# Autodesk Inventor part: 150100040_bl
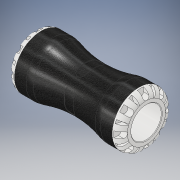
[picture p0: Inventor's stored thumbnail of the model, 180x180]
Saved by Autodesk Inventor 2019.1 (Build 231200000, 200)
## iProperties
Created: 2016-12
Part Number: 150100040_bl
Material: PVC-Piping
Description: PLASSON G-PLASS COUPLING 40X40
Document SubType Name: Modeling
Designer: KIM
Mass: 95.2094 g
Surface Area: 200.83 cm^2
Volume: 68.0067 cm^3
Density: 1.4 g/cm^3
Appearance: White
ILogicFactory: False
Author: KIM
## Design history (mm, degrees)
derived "150100.ipt"
feature "Solid1::150100.ipt" dims "ScaleForDerivedMember" = 10
tag "TaggingFeature1"
body "Solid1"
other parameters: "d2" = 73 [user parameter], "d4" = 3.33333 [user parameter], "d11" = 8 [user parameter], "d13" = 8 [user parameter], "d14" = 0 [user parameter], "d16" = 360 deg [user parameter], "d18" = 8 deg [user parameter], "d19" = 0.8 [user parameter], "d20" = 8 deg [user parameter], "d21" = 0.8 [user parameter], "d23" = 0 [user parameter], "d25" = 360 deg [user parameter], "d27" = 28 [user parameter], "d29" = 12 [user parameter], "d30" = 16 [user parameter], "d31" = 0 [user parameter], "d33" = 0 [user parameter], "d37" = 29.6 [user parameter], "d38" = 0.7 [user parameter], "d43" = 5 [user parameter], "d45" = 29.6 [user parameter], "d46" = 56 [user parameter], "d48" = 148 [user parameter], "d50" = 360 deg [user parameter], "d54" = 0.513 [user parameter], "H_" = 148 [user parameter], "l_" = 73 [user parameter]
